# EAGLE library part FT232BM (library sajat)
FT232BM USB-RS232 Wandler FTDI
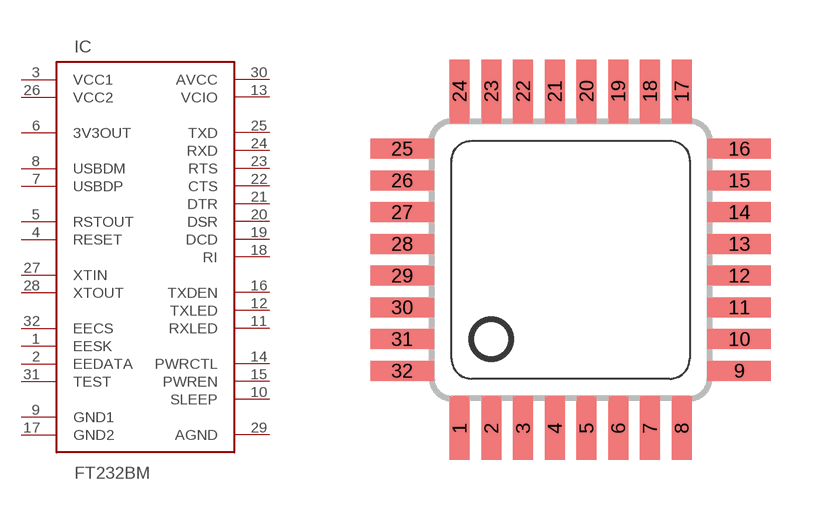
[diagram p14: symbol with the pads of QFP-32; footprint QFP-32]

Designator prefix IC

## FT232BM  [QFP-32]
1  EESK
2  EEDATA
3  VCC1  pwr
4  RESET  in
5  RSTOUT  out
6  3V3OUT  out
7  USBDP
8  USBDM
9  GND1  sup
10  SLEEP  out
11  RXLED  oc
12  TXLED  oc
13  VCIO  in
14  PWRCTL  in
15  PWREN  out
16  TXDEN  out
17  GND2  sup
18  RI  in
19  DCD  in
20  DSR  in
21  DTR  out
22  CTS  in
23  RTS  out
24  RXD  in
25  TXD  out
26  VCC2  pwr
27  XTIN  in
28  XTOUT  out
29  AGND  in
30  AVCC  in
31  TEST  in
32  EECS

## Footprint QFP-32 (pad centres in mm)
Gehäuse QFP-32
smd 0.508 x 1.6: 1 -2.8,-4.25; 2 -2,-4.25; 3 -1.2,-4.25; 4 -0.4,-4.25; 5 0.4,-4.25; 6 1.2,-4.25; 7 2,-4.25; 8 2.8,-4.25; 17 2.8,4.25; 18 2,4.25; 19 1.2,4.25; 20 0.4,4.25; 21 -0.4,4.25; 22 -1.2,4.25; 23 -2,4.25; 24 -2.8,4.25
smd 1.6 x 0.508: 9 4.25,-2.8; 10 4.25,-2; 11 4.25,-1.2; 12 4.25,-0.4; 13 4.25,0.4; 14 4.25,1.2; 15 4.25,2; 16 4.25,2.8; 25 -4.25,2.8; 26 -4.25,2; 27 -4.25,1.2; 28 -4.25,0.4; 29 -4.25,-0.4; 30 -4.25,-1.2; 31 -4.25,-2; 32 -4.25,-2.8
